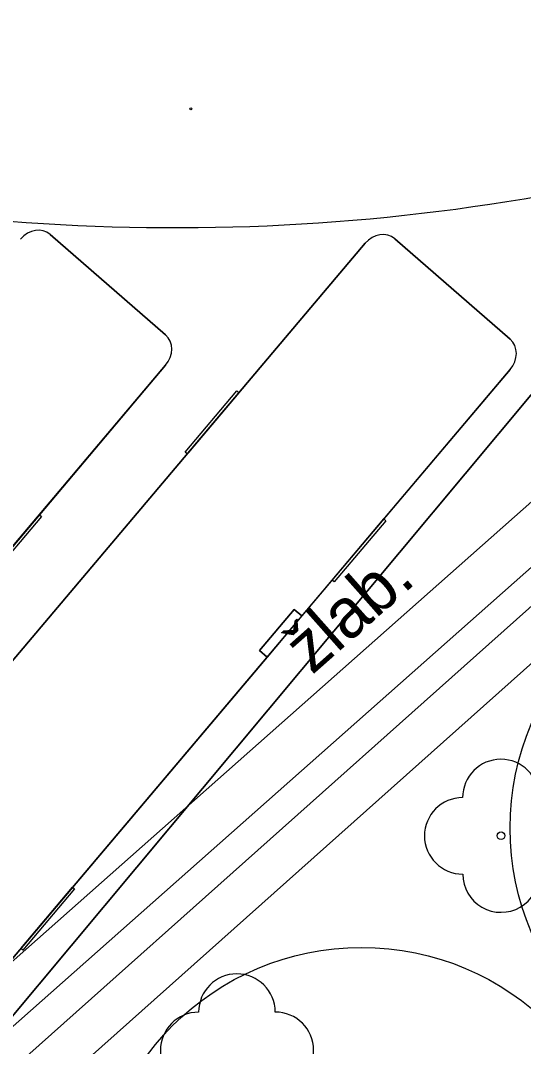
# Model space of a CAD drawing. Extents: x -438303 to -437792, y -1133191 to -1132731.
# Drawn here: x -438059.93 to -438053.37, y -1132989.77 to -1132976.36 of the extents above; entities that cross this region are included whole.
import ezdxf

# ---------------------------------------------------------------- set-up
doc = ezdxf.new("R2010")
doc.units = 0
for name, color, linetype in [('Vrstva 1', 7, 'Continuous'), ('Vrstva 10', 7, 'Continuous'), ('Vrstva 11', 7, 'Continuous'), ('Vrstva 22', 7, 'Continuous'), ('Vrstva 40', 7, 'Continuous'), ('Vrstva 9', 7, 'Continuous')]:
    doc.layers.add(name, color=color, linetype=linetype)

msp = doc.modelspace()

# ---------------------------------------------------------------- linework, layer by layer
at = {"layer": 'Vrstva 1'}
for p, q in [((-438059.548, -1132979.156), (-438058.04, -1132980.469)), ((-438059.548, -1132979.156), (-438058.04, -1132980.469)), ((-438055.049, -1132979.212), (-438053.541, -1132980.525)), ((-438055.049, -1132979.212), (-438053.541, -1132980.525))]:
    msp.add_line(p, q, dxfattribs=at)
for points in [[(-438050.697, -1132978.171), (-438060.995, -1132990.509), (-438063.682, -1132988.266), (-438065.334, -1132990.246)], [(-438050.697, -1132978.171), (-438060.995, -1132990.509), (-438063.682, -1132988.266), (-438065.334, -1132990.246)], [(-438058.04, -1132980.469), (-438059.548, -1132979.156)], [(-438058.04, -1132980.469), (-438059.548, -1132979.156)], [(-438062.75, -1132988.071), (-438062.103, -1132987.166), (-438055.436, -1132979.272)], [(-438062.75, -1132988.071), (-438062.103, -1132987.166), (-438055.436, -1132979.272)], [(-438055.436, -1132979.272), (-438062.103, -1132987.166)], [(-438055.436, -1132979.272), (-438062.103, -1132987.166)], [(-438053.541, -1132980.525), (-438055.049, -1132979.212)], [(-438053.541, -1132980.525), (-438055.049, -1132979.212)], [(-438058.04, -1132980.867), (-438060.76, -1132984.087), (-438060.86, -1132984), (-438061.313, -1132984.538), (-438061.214, -1132984.624), (-438064.707, -1132988.761), (-438064.716, -1132988.769), (-438064.815, -1132988.683), (-438065.359, -1132989.225), (-438065.257, -1132989.314), (-438065.49, -1132989.549)], [(-438058.04, -1132980.867), (-438060.76, -1132984.087), (-438060.86, -1132984), (-438061.313, -1132984.538), (-438061.214, -1132984.624), (-438064.707, -1132988.761), (-438064.716, -1132988.769), (-438064.815, -1132988.683), (-438065.359, -1132989.225), (-438065.257, -1132989.314), (-438065.49, -1132989.549)], [(-438064.707, -1132988.761), (-438058.04, -1132980.867)], [(-438064.707, -1132988.761), (-438058.04, -1132980.867)], [(-438053.541, -1132980.922), (-438056.261, -1132984.142), (-438056.36, -1132984.056), (-438056.814, -1132984.593), (-438056.714, -1132984.68), (-438060.208, -1132988.816), (-438060.216, -1132988.824), (-438060.315, -1132988.738), (-438060.86, -1132989.281), (-438060.758, -1132989.37), (-438060.99, -1132989.604)], [(-438053.541, -1132980.922), (-438056.261, -1132984.142), (-438056.36, -1132984.056), (-438056.814, -1132984.593), (-438056.714, -1132984.68), (-438060.208, -1132988.816), (-438060.216, -1132988.824), (-438060.315, -1132988.738), (-438060.86, -1132989.281), (-438060.758, -1132989.37), (-438060.99, -1132989.604)], [(-438060.208, -1132988.816), (-438053.541, -1132980.922)], [(-438060.208, -1132988.816), (-438053.541, -1132980.922)]]:
    msp.add_lwpolyline(points, dxfattribs=at)
for points in [[(-438057.085, -1132981.225), (-438057.761, -1132982.025), (-438057.787, -1132982.003), (-438057.111, -1132981.202)], [(-438057.085, -1132981.225), (-438057.761, -1132982.025), (-438057.787, -1132982.003), (-438057.111, -1132981.202)], [(-438057.085, -1132981.225), (-438057.743, -1132982.004), (-438057.743, -1132982.004), (-438057.085, -1132981.225)], [(-438057.085, -1132981.225), (-438057.743, -1132982.004), (-438057.743, -1132982.004), (-438057.085, -1132981.225)], [(-438059.663, -1132982.842), (-438060.339, -1132983.643), (-438060.365, -1132983.62), (-438059.689, -1132982.82)], [(-438059.663, -1132982.842), (-438060.339, -1132983.643), (-438060.365, -1132983.62), (-438059.689, -1132982.82)], [(-438055.164, -1132982.898), (-438055.84, -1132983.698), (-438055.866, -1132983.675), (-438055.19, -1132982.875)], [(-438055.164, -1132982.898), (-438055.84, -1132983.698), (-438055.866, -1132983.675), (-438055.19, -1132982.875)], [(-438056.261, -1132984.142), (-438056.714, -1132984.68), (-438056.814, -1132984.593), (-438056.36, -1132984.056)], [(-438056.261, -1132984.142), (-438056.714, -1132984.68), (-438056.814, -1132984.593), (-438056.36, -1132984.056)], [(-438059.229, -1132987.71), (-438059.905, -1132988.511), (-438059.931, -1132988.488), (-438059.255, -1132987.688)], [(-438059.229, -1132987.71), (-438059.905, -1132988.511), (-438059.931, -1132988.488), (-438059.255, -1132987.688)]]:
    msp.add_lwpolyline(points, close=True, dxfattribs=at)
msp.add_circle((-438057.71, -1132977.514), 0.0127, dxfattribs=at)
msp.add_circle((-438057.71, -1132977.514), 0.0127, dxfattribs=at)
msp.add_circle((-438057.71, -1132977.514), 0.0127, dxfattribs=at)
msp.add_circle((-438057.71, -1132977.514), 0.0127, dxfattribs=at)
msp.add_arc((-438057.911, -1132951.468), 27.6, 255.1809, 285.1197, dxfattribs=at)
msp.add_arc((-438057.911, -1132951.468), 27.6, 255.1809, 285.1197, dxfattribs=at)
for centre, start_param, end_param in [((-438059.741, -1132979.386), 3.093695, 4.664491), ((-438059.741, -1132979.386), 3.093695, 4.664491), ((-438059.741, -1132979.386), 3.093695, 4.664491), ((-438059.741, -1132979.386), 3.093695, 4.664491), ((-438055.242, -1132979.441), 3.093695, 4.664491), ((-438055.242, -1132979.441), 3.093695, 4.664491), ((-438055.242, -1132979.441), 3.093695, 4.664491), ((-438055.242, -1132979.441), 3.093695, 4.664491), ((-438058.234, -1132980.698), 1.522899, 3.093695), ((-438058.234, -1132980.698), 1.522899, 3.093695), ((-438058.234, -1132980.698), 1.522899, 3.093695), ((-438058.234, -1132980.698), 1.522899, 3.093695), ((-438053.734, -1132980.754), 1.522899, 3.093695), ((-438053.734, -1132980.754), 1.522899, 3.093695), ((-438053.734, -1132980.754), 1.522899, 3.093695), ((-438053.734, -1132980.754), 1.522899, 3.093695)]:
    msp.add_ellipse(centre, major_axis=(-0.184, -0.237), ratio=0.855, start_param=start_param, end_param=end_param, dxfattribs=at)
at = {"layer": 'Vrstva 10'}
msp.add_lwpolyline([(-438035.376, -1132968.181), (-438040.49, -1132972.647), (-438048.755, -1132979.99), (-438064.924, -1132994.417), (-438072.55, -1133001.015), (-438073.819, -1133001.824), (-438074.934, -1133002.283), (-438076.129, -1133002.536)], dxfattribs=at)
at = {"layer": 'Vrstva 11'}
for points in [[(-438073.846, -1133000.884), (-438049.346, -1132979.178), (-438041.204, -1132972.05), (-438034.947, -1132966.333)], [(-438064.679, -1132993.618), (-438048.923, -1132979.658), (-438040.777, -1132972.527), (-438034.481, -1132966.775)]]:
    msp.add_lwpolyline(points, dxfattribs=at)
at = {"layer": 'Vrstva 22'}
msp.add_circle((-438053.661, -1132987.015), 0.05, dxfattribs=at)
for centre, start, end in [((-438053.662, -1132986.515), 0.1042, 180.1042), ((-438054.161, -1132987.016), 90.1042, 270.1042), ((-438053.66, -1132987.515), 180.1042, 0.1042), ((-438057.109, -1132989.319), 0.1042, 180.1042), ((-438057.608, -1132989.82), 90.1042, 270.1042), ((-438056.608, -1132989.818), 270.1042, 90.1042)]:
    msp.add_arc(centre, 0.5, start, end, dxfattribs=at)
at = {"layer": 'Vrstva 40'}
for points in [[(-438006.517, -1132950.825), (-438080.128, -1133015.753), (-438085.047, -1133011.675), (-438080.396, -1133006.399), (-438083.987, -1133003.228), (-438082.355, -1133001.381), (-438077.033, -1133005.821), (-438076.406, -1133006.347), (-438075.765, -1133005.58), (-438066.274, -1132994.076), (-438072.916, -1132988.399), (-438072.237, -1132987.605), (-438069.545, -1132989.828), (-438068.169, -1132988.18), (-438065.482, -1132990.423), (-438063.682, -1132988.266), (-438060.995, -1132990.509), (-438050.697, -1132978.171), (-438047.623, -1132977.126), (-438045.11, -1132975.925), (-438042.586, -1132974.412), (-438040.838, -1132973.158)], [(-438006.517, -1132950.825), (-438080.128, -1133015.753), (-438082.213, -1133013.389), (-438066.274, -1132994.076), (-438072.916, -1132988.399), (-438072.237, -1132987.605), (-438069.545, -1132989.828), (-438068.169, -1132988.18), (-438065.482, -1132990.423), (-438063.682, -1132988.266), (-438060.995, -1132990.509), (-438050.697, -1132978.171), (-438047.623, -1132977.126), (-438045.11, -1132975.925), (-438042.586, -1132974.412), (-438040.838, -1132973.158)]]:
    msp.add_lwpolyline(points, dxfattribs=at)
for centre in [(-438050.052, -1132986.914), (-438055.482, -1132991.963)]:
    msp.add_circle(centre, 3.489, dxfattribs=at)
at = {"layer": 'Vrstva 9'}
msp.add_lwpolyline([(-438046.89, -1132979.081), (-438048.384, -1132980.408), (-438063.5, -1132993.895)], dxfattribs=at)

# ---------------------------------------------------------------- texts
at = {"layer": 'Vrstva 40'}
msp.add_text('žlab.', height=0.65, rotation=41.5409, dxfattribs=at).set_placement((-438056.128, -1132984.919))

doc.saveas('drawing.dxf')
